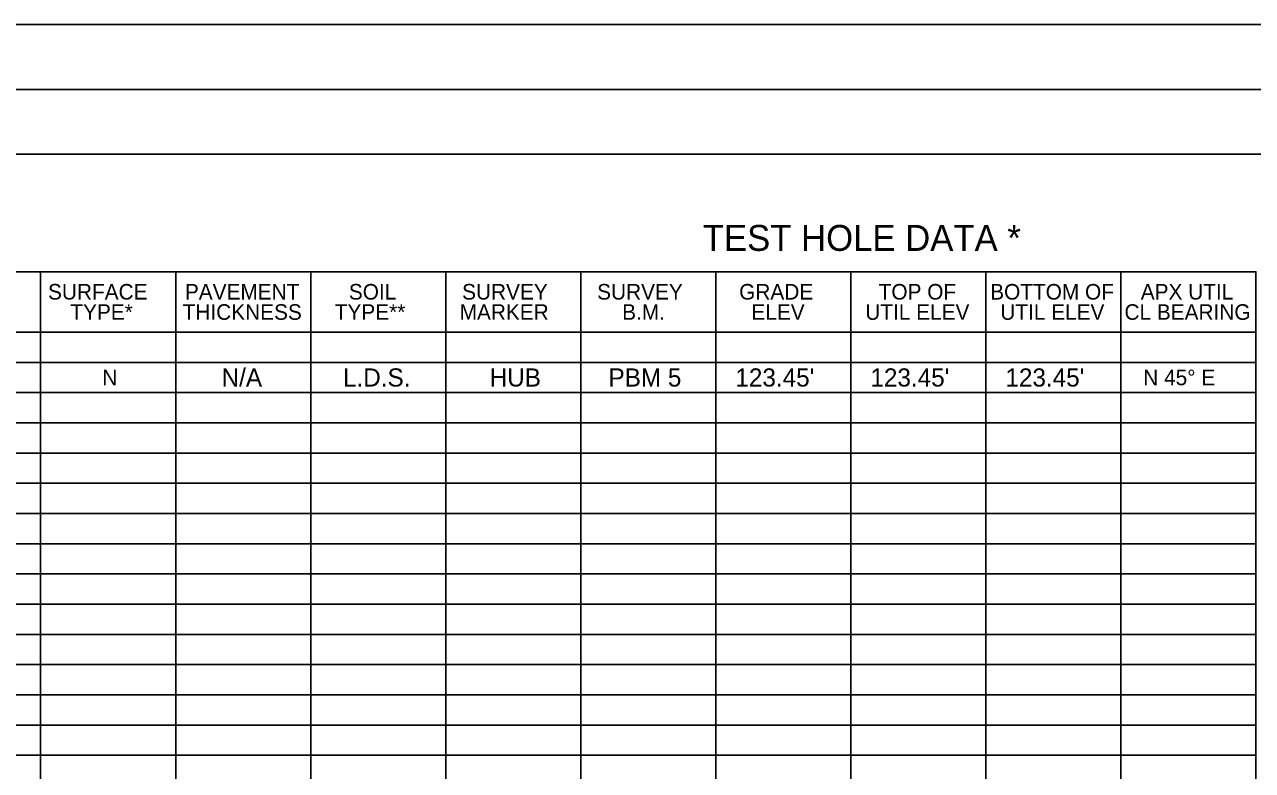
# Model space of a CAD drawing. Extents: x 14330 to 16126, y 15844 to 16994.
# Drawn here: x 14825 to 15298.3, y 16706 to 16993.6 of the extents above; entities that cross this region are included whole.
import ezdxf

# ---------------------------------------------------------------- set-up
doc = ezdxf.new("R2010")
doc.units = 0
for name, color, linetype in [('RD_SHT_Bndy', 7, 'Continuous'), ('RD_SHT_Iplotshp', 7, 'Continuous'), ('RD_SHT_TX', 7, 'Continuous')]:
    doc.layers.add(name, color=color, linetype=linetype)

msp = doc.modelspace()

# ---------------------------------------------------------------- linework, layer by layer
at = {"layer": 'RD_SHT_Bndy'}
for p, q in [((16108.25, 16993.63), (14348.25, 16993.63)), ((16108.25, 16968.63), (14348.25, 16968.63)), ((16105.85, 16943.63), (14430.85, 16943.63))]:
    msp.add_line(p, q, dxfattribs=at)
for points in [[(14779.19, 16875.02), (14831.23, 16875.02), (14831.23, 16898.33), (14779.19, 16898.33)], [(14831.23, 16875.02), (14883.27, 16875.02), (14883.27, 16898.33), (14831.23, 16898.33)], [(14883.27, 16875.02), (14935.31, 16875.02), (14935.31, 16898.33), (14883.27, 16898.33)], [(14935.31, 16875.02), (14987.35, 16875.02), (14987.35, 16898.33), (14935.31, 16898.33)], [(14987.35, 16875.02), (15039.39, 16875.02), (15039.39, 16898.33), (14987.35, 16898.33)], [(15039.39, 16875.02), (15091.44, 16875.02), (15091.44, 16898.33), (15039.39, 16898.33)], [(15091.44, 16875.02), (15143.48, 16875.02), (15143.48, 16898.33), (15091.44, 16898.33)], [(15143.48, 16875.02), (15195.52, 16875.02), (15195.52, 16898.33), (15143.48, 16898.33)], [(15195.52, 16875.02), (15247.56, 16875.02), (15247.56, 16898.33), (15195.52, 16898.33)], [(15247.56, 16875.02), (15299.6, 16875.02), (15299.6, 16898.33), (15247.56, 16898.33)], [(14831.23, 16863.36), (14779.19, 16863.36), (14779.19, 16875.02), (14831.23, 16875.02)], [(14883.27, 16863.36), (14831.23, 16863.36), (14831.23, 16875.02), (14883.27, 16875.02)], [(14935.31, 16863.36), (14883.27, 16863.36), (14883.27, 16875.02), (14935.31, 16875.02)], [(14987.35, 16863.36), (14935.31, 16863.36), (14935.31, 16875.02), (14987.35, 16875.02)], [(15039.39, 16863.36), (14987.35, 16863.36), (14987.35, 16875.02), (15039.39, 16875.02)], [(15091.44, 16863.36), (15039.39, 16863.36), (15039.39, 16875.02), (15091.44, 16875.02)], [(15143.48, 16863.36), (15091.44, 16863.36), (15091.44, 16875.02), (15143.48, 16875.02)], [(15195.52, 16863.36), (15143.48, 16863.36), (15143.48, 16875.02), (15195.52, 16875.02)], [(15247.56, 16863.36), (15195.52, 16863.36), (15195.52, 16875.02), (15247.56, 16875.02)], [(15299.6, 16863.36), (15247.56, 16863.36), (15247.56, 16875.02), (15299.6, 16875.02)], [(14831.23, 16851.71), (14779.19, 16851.71), (14779.19, 16863.36), (14831.23, 16863.36)], [(14883.27, 16851.71), (14831.23, 16851.71), (14831.23, 16863.36), (14883.27, 16863.36)], [(14935.31, 16851.71), (14883.27, 16851.71), (14883.27, 16863.36), (14935.31, 16863.36)], [(14987.35, 16851.71), (14935.31, 16851.71), (14935.31, 16863.36), (14987.35, 16863.36)], [(15039.39, 16851.71), (14987.35, 16851.71), (14987.35, 16863.36), (15039.39, 16863.36)], [(15091.44, 16851.71), (15039.39, 16851.71), (15039.39, 16863.36), (15091.44, 16863.36)], [(15143.48, 16851.71), (15091.44, 16851.71), (15091.44, 16863.36), (15143.48, 16863.36)], [(15195.52, 16851.71), (15143.48, 16851.71), (15143.48, 16863.36), (15195.52, 16863.36)], [(15247.56, 16851.71), (15195.52, 16851.71), (15195.52, 16863.36), (15247.56, 16863.36)], [(15299.6, 16851.71), (15247.56, 16851.71), (15247.56, 16863.36), (15299.6, 16863.36)], [(14831.23, 16840.05), (14779.19, 16840.05), (14779.19, 16851.71), (14831.23, 16851.71)], [(14883.27, 16840.05), (14831.23, 16840.05), (14831.23, 16851.71), (14883.27, 16851.71)], [(14935.31, 16840.05), (14883.27, 16840.05), (14883.27, 16851.71), (14935.31, 16851.71)], [(14987.35, 16840.05), (14935.31, 16840.05), (14935.31, 16851.71), (14987.35, 16851.71)], [(15039.39, 16840.05), (14987.35, 16840.05), (14987.35, 16851.71), (15039.39, 16851.71)], [(15091.44, 16840.05), (15039.39, 16840.05), (15039.39, 16851.71), (15091.44, 16851.71)], [(15143.48, 16840.05), (15091.44, 16840.05), (15091.44, 16851.71), (15143.48, 16851.71)], [(15195.52, 16840.05), (15143.48, 16840.05), (15143.48, 16851.71), (15195.52, 16851.71)], [(15247.56, 16840.05), (15195.52, 16840.05), (15195.52, 16851.71), (15247.56, 16851.71)], [(15299.6, 16840.05), (15247.56, 16840.05), (15247.56, 16851.71), (15299.6, 16851.71)], [(14831.23, 16828.4), (14779.19, 16828.4), (14779.19, 16840.05), (14831.23, 16840.05)], [(14883.27, 16828.4), (14831.23, 16828.4), (14831.23, 16840.05), (14883.27, 16840.05)], [(14935.31, 16828.4), (14883.27, 16828.4), (14883.27, 16840.05), (14935.31, 16840.05)], [(14987.35, 16828.4), (14935.31, 16828.4), (14935.31, 16840.05), (14987.35, 16840.05)], [(15039.39, 16828.4), (14987.35, 16828.4), (14987.35, 16840.05), (15039.39, 16840.05)], [(15091.44, 16828.4), (15039.39, 16828.4), (15039.39, 16840.05), (15091.44, 16840.05)], [(15143.48, 16828.4), (15091.44, 16828.4), (15091.44, 16840.05), (15143.48, 16840.05)], [(15195.52, 16828.4), (15143.48, 16828.4), (15143.48, 16840.05), (15195.52, 16840.05)], [(15247.56, 16828.4), (15195.52, 16828.4), (15195.52, 16840.05), (15247.56, 16840.05)], [(15299.6, 16828.4), (15247.56, 16828.4), (15247.56, 16840.05), (15299.6, 16840.05)], [(14831.23, 16816.74), (14779.19, 16816.74), (14779.19, 16828.4), (14831.23, 16828.4)], [(14883.27, 16816.74), (14831.23, 16816.74), (14831.23, 16828.4), (14883.27, 16828.4)], [(14935.31, 16816.74), (14883.27, 16816.74), (14883.27, 16828.4), (14935.31, 16828.4)], [(14987.35, 16816.74), (14935.31, 16816.74), (14935.31, 16828.4), (14987.35, 16828.4)], [(15039.39, 16816.74), (14987.35, 16816.74), (14987.35, 16828.4), (15039.39, 16828.4)], [(15091.44, 16816.74), (15039.39, 16816.74), (15039.39, 16828.4), (15091.44, 16828.4)], [(15143.48, 16816.74), (15091.44, 16816.74), (15091.44, 16828.4), (15143.48, 16828.4)], [(15195.52, 16816.74), (15143.48, 16816.74), (15143.48, 16828.4), (15195.52, 16828.4)], [(15247.56, 16816.74), (15195.52, 16816.74), (15195.52, 16828.4), (15247.56, 16828.4)], [(15299.6, 16816.74), (15247.56, 16816.74), (15247.56, 16828.4), (15299.6, 16828.4)], [(14831.23, 16805.09), (14779.19, 16805.09), (14779.19, 16816.74), (14831.23, 16816.74)], [(14883.27, 16805.09), (14831.23, 16805.09), (14831.23, 16816.74), (14883.27, 16816.74)], [(14935.31, 16805.09), (14883.27, 16805.09), (14883.27, 16816.74), (14935.31, 16816.74)], [(14987.35, 16805.09), (14935.31, 16805.09), (14935.31, 16816.74), (14987.35, 16816.74)], [(15039.39, 16805.09), (14987.35, 16805.09), (14987.35, 16816.74), (15039.39, 16816.74)], [(15091.44, 16805.09), (15039.39, 16805.09), (15039.39, 16816.74), (15091.44, 16816.74)], [(15143.48, 16805.09), (15091.44, 16805.09), (15091.44, 16816.74), (15143.48, 16816.74)], [(15195.52, 16805.09), (15143.48, 16805.09), (15143.48, 16816.74), (15195.52, 16816.74)], [(15247.56, 16805.09), (15195.52, 16805.09), (15195.52, 16816.74), (15247.56, 16816.74)], [(15299.6, 16805.09), (15247.56, 16805.09), (15247.56, 16816.74), (15299.6, 16816.74)], [(14831.23, 16793.43), (14779.19, 16793.43), (14779.19, 16805.09), (14831.23, 16805.09)], [(14883.27, 16793.43), (14831.23, 16793.43), (14831.23, 16805.09), (14883.27, 16805.09)], [(14935.31, 16793.43), (14883.27, 16793.43), (14883.27, 16805.09), (14935.31, 16805.09)], [(14987.35, 16793.43), (14935.31, 16793.43), (14935.31, 16805.09), (14987.35, 16805.09)], [(15039.39, 16793.43), (14987.35, 16793.43), (14987.35, 16805.09), (15039.39, 16805.09)], [(15091.44, 16793.43), (15039.39, 16793.43), (15039.39, 16805.09), (15091.44, 16805.09)], [(15143.48, 16793.43), (15091.44, 16793.43), (15091.44, 16805.09), (15143.48, 16805.09)], [(15195.52, 16793.43), (15143.48, 16793.43), (15143.48, 16805.09), (15195.52, 16805.09)], [(15247.56, 16793.43), (15195.52, 16793.43), (15195.52, 16805.09), (15247.56, 16805.09)], [(15299.6, 16793.43), (15247.56, 16793.43), (15247.56, 16805.09), (15299.6, 16805.09)], [(14831.23, 16781.78), (14779.19, 16781.78), (14779.19, 16793.43), (14831.23, 16793.43)], [(14883.27, 16781.78), (14831.23, 16781.78), (14831.23, 16793.43), (14883.27, 16793.43)], [(14935.31, 16781.78), (14883.27, 16781.78), (14883.27, 16793.43), (14935.31, 16793.43)], [(14987.35, 16781.78), (14935.31, 16781.78), (14935.31, 16793.43), (14987.35, 16793.43)], [(15039.39, 16781.78), (14987.35, 16781.78), (14987.35, 16793.43), (15039.39, 16793.43)], [(15091.44, 16781.78), (15039.39, 16781.78), (15039.39, 16793.43), (15091.44, 16793.43)], [(15143.48, 16781.78), (15091.44, 16781.78), (15091.44, 16793.43), (15143.48, 16793.43)], [(15195.52, 16781.78), (15143.48, 16781.78), (15143.48, 16793.43), (15195.52, 16793.43)], [(15247.56, 16781.78), (15195.52, 16781.78), (15195.52, 16793.43), (15247.56, 16793.43)], [(15299.6, 16781.78), (15247.56, 16781.78), (15247.56, 16793.43), (15299.6, 16793.43)], [(14831.23, 16770.12), (14779.19, 16770.12), (14779.19, 16781.78), (14831.23, 16781.78)], [(14883.27, 16770.12), (14831.23, 16770.12), (14831.23, 16781.78), (14883.27, 16781.78)], [(14935.31, 16770.12), (14883.27, 16770.12), (14883.27, 16781.78), (14935.31, 16781.78)], [(14987.35, 16770.12), (14935.31, 16770.12), (14935.31, 16781.78), (14987.35, 16781.78)], [(15039.39, 16770.12), (14987.35, 16770.12), (14987.35, 16781.78), (15039.39, 16781.78)], [(15091.44, 16770.12), (15039.39, 16770.12), (15039.39, 16781.78), (15091.44, 16781.78)], [(15143.48, 16770.12), (15091.44, 16770.12), (15091.44, 16781.78), (15143.48, 16781.78)], [(15195.52, 16770.12), (15143.48, 16770.12), (15143.48, 16781.78), (15195.52, 16781.78)], [(15247.56, 16770.12), (15195.52, 16770.12), (15195.52, 16781.78), (15247.56, 16781.78)], [(15299.6, 16770.12), (15247.56, 16770.12), (15247.56, 16781.78), (15299.6, 16781.78)], [(14831.23, 16758.47), (14779.19, 16758.47), (14779.19, 16770.12), (14831.23, 16770.12)], [(14883.27, 16758.47), (14831.23, 16758.47), (14831.23, 16770.12), (14883.27, 16770.12)], [(14935.31, 16758.47), (14883.27, 16758.47), (14883.27, 16770.12), (14935.31, 16770.12)], [(14987.35, 16758.47), (14935.31, 16758.47), (14935.31, 16770.12), (14987.35, 16770.12)], [(15039.39, 16758.47), (14987.35, 16758.47), (14987.35, 16770.12), (15039.39, 16770.12)], [(15091.44, 16758.47), (15039.39, 16758.47), (15039.39, 16770.12), (15091.44, 16770.12)], [(15143.48, 16758.47), (15091.44, 16758.47), (15091.44, 16770.12), (15143.48, 16770.12)], [(15195.52, 16758.47), (15143.48, 16758.47), (15143.48, 16770.12), (15195.52, 16770.12)], [(15247.56, 16758.47), (15195.52, 16758.47), (15195.52, 16770.12), (15247.56, 16770.12)], [(15299.6, 16758.47), (15247.56, 16758.47), (15247.56, 16770.12), (15299.6, 16770.12)], [(14831.23, 16746.81), (14779.19, 16746.81), (14779.19, 16758.47), (14831.23, 16758.47)], [(14883.27, 16746.81), (14831.23, 16746.81), (14831.23, 16758.47), (14883.27, 16758.47)], [(14935.31, 16746.81), (14883.27, 16746.81), (14883.27, 16758.47), (14935.31, 16758.47)], [(14987.35, 16746.81), (14935.31, 16746.81), (14935.31, 16758.47), (14987.35, 16758.47)], [(15039.39, 16746.81), (14987.35, 16746.81), (14987.35, 16758.47), (15039.39, 16758.47)], [(15091.44, 16746.81), (15039.39, 16746.81), (15039.39, 16758.47), (15091.44, 16758.47)], [(15143.48, 16746.81), (15091.44, 16746.81), (15091.44, 16758.47), (15143.48, 16758.47)], [(15195.52, 16746.81), (15143.48, 16746.81), (15143.48, 16758.47), (15195.52, 16758.47)], [(15247.56, 16746.81), (15195.52, 16746.81), (15195.52, 16758.47), (15247.56, 16758.47)], [(15299.6, 16746.81), (15247.56, 16746.81), (15247.56, 16758.47), (15299.6, 16758.47)], [(14831.23, 16735.16), (14779.19, 16735.16), (14779.19, 16746.81), (14831.23, 16746.81)], [(14883.27, 16735.16), (14831.23, 16735.16), (14831.23, 16746.81), (14883.27, 16746.81)], [(14935.31, 16735.16), (14883.27, 16735.16), (14883.27, 16746.81), (14935.31, 16746.81)], [(14987.35, 16735.16), (14935.31, 16735.16), (14935.31, 16746.81), (14987.35, 16746.81)], [(15039.39, 16735.16), (14987.35, 16735.16), (14987.35, 16746.81), (15039.39, 16746.81)], [(15091.44, 16735.16), (15039.39, 16735.16), (15039.39, 16746.81), (15091.44, 16746.81)], [(15143.48, 16735.16), (15091.44, 16735.16), (15091.44, 16746.81), (15143.48, 16746.81)], [(15195.52, 16735.16), (15143.48, 16735.16), (15143.48, 16746.81), (15195.52, 16746.81)], [(15247.56, 16735.16), (15195.52, 16735.16), (15195.52, 16746.81), (15247.56, 16746.81)], [(15299.6, 16735.16), (15247.56, 16735.16), (15247.56, 16746.81), (15299.6, 16746.81)], [(14831.23, 16723.5), (14779.19, 16723.5), (14779.19, 16735.16), (14831.23, 16735.16)], [(14883.27, 16723.5), (14831.23, 16723.5), (14831.23, 16735.16), (14883.27, 16735.16)], [(14935.31, 16723.5), (14883.27, 16723.5), (14883.27, 16735.16), (14935.31, 16735.16)], [(14987.35, 16723.5), (14935.31, 16723.5), (14935.31, 16735.16), (14987.35, 16735.16)], [(15039.39, 16723.5), (14987.35, 16723.5), (14987.35, 16735.16), (15039.39, 16735.16)], [(15091.44, 16723.5), (15039.39, 16723.5), (15039.39, 16735.16), (15091.44, 16735.16)], [(15143.48, 16723.5), (15091.44, 16723.5), (15091.44, 16735.16), (15143.48, 16735.16)], [(15195.52, 16723.5), (15143.48, 16723.5), (15143.48, 16735.16), (15195.52, 16735.16)], [(15247.56, 16723.5), (15195.52, 16723.5), (15195.52, 16735.16), (15247.56, 16735.16)], [(15299.6, 16723.5), (15247.56, 16723.5), (15247.56, 16735.16), (15299.6, 16735.16)], [(14831.23, 16711.84), (14779.19, 16711.84), (14779.19, 16723.5), (14831.23, 16723.5)], [(14883.27, 16711.84), (14831.23, 16711.84), (14831.23, 16723.5), (14883.27, 16723.5)], [(14935.31, 16711.84), (14883.27, 16711.84), (14883.27, 16723.5), (14935.31, 16723.5)], [(14987.35, 16711.84), (14935.31, 16711.84), (14935.31, 16723.5), (14987.35, 16723.5)], [(15039.39, 16711.84), (14987.35, 16711.84), (14987.35, 16723.5), (15039.39, 16723.5)], [(15091.44, 16711.84), (15039.39, 16711.84), (15039.39, 16723.5), (15091.44, 16723.5)], [(15143.48, 16711.84), (15091.44, 16711.84), (15091.44, 16723.5), (15143.48, 16723.5)], [(15195.52, 16711.84), (15143.48, 16711.84), (15143.48, 16723.5), (15195.52, 16723.5)], [(15247.56, 16711.84), (15195.52, 16711.84), (15195.52, 16723.5), (15247.56, 16723.5)], [(15299.6, 16711.84), (15247.56, 16711.84), (15247.56, 16723.5), (15299.6, 16723.5)], [(14831.23, 16700.19), (14779.19, 16700.19), (14779.19, 16711.84), (14831.23, 16711.84)], [(14883.27, 16700.19), (14831.23, 16700.19), (14831.23, 16711.84), (14883.27, 16711.84)], [(14935.31, 16700.19), (14883.27, 16700.19), (14883.27, 16711.84), (14935.31, 16711.84)], [(14987.35, 16700.19), (14935.31, 16700.19), (14935.31, 16711.84), (14987.35, 16711.84)], [(15039.39, 16700.19), (14987.35, 16700.19), (14987.35, 16711.84), (15039.39, 16711.84)], [(15091.44, 16700.19), (15039.39, 16700.19), (15039.39, 16711.84), (15091.44, 16711.84)], [(15143.48, 16700.19), (15091.44, 16700.19), (15091.44, 16711.84), (15143.48, 16711.84)], [(15195.52, 16700.19), (15143.48, 16700.19), (15143.48, 16711.84), (15195.52, 16711.84)], [(15247.56, 16700.19), (15195.52, 16700.19), (15195.52, 16711.84), (15247.56, 16711.84)], [(15299.6, 16700.19), (15247.56, 16700.19), (15247.56, 16711.84), (15299.6, 16711.84)]]:
    msp.add_lwpolyline(points, close=True, dxfattribs=at)
at = {"layer": 'RD_SHT_Iplotshp'}
msp.add_lwpolyline([(14329.65, 16968.63), (16125.65, 16968.63), (16125.65, 15868.63), (14329.65, 15868.63)], close=True, dxfattribs=at)

# ---------------------------------------------------------------- texts
at = {"layer": 'RD_SHT_TX'}
for s, height, p in [('TEST HOLE DATA *', 10, (15086.42, 16906.35)), ('SURFACE', 6, (14834.07, 16887.58)), ('PAVEMENT', 6, (14886.82, 16887.58)), ('SOIL', 6, (14950.02, 16887.58)), ('SURVEY', 6, (14993.67, 16887.58)), ('SURVEY', 6, (15045.72, 16887.58)), ('GRADE', 6, (15100.45, 16887.58)), ('TOP OF', 6, (15154.22, 16887.58)), ('BOTTOM OF', 6, (15197.2, 16887.58)), ('APX UTIL', 6, (15255.24, 16887.58)), ('TYPE*', 6, (14842.68, 16879.77)), ('THICKNESS', 6, (14885.97, 16879.77)), ('TYPE**', 6, (14944.58, 16879.77)), ('MARKER', 6, (14992.72, 16879.77)), ('B.M.', 6, (15055.35, 16879.77)), ('ELEV', 6, (15105.18, 16879.77)), ('UTIL ELEV', 6, (15149.06, 16879.77)), ('UTIL ELEV', 6, (15201.1, 16879.77)), ('CL BEARING', 6, (15248.95, 16879.77)), ('N', 6, (14854.98, 16854.53)), ('N/A', 7, (14900.97, 16854.03)), ('L.D.S.', 7, (14947.75, 16854.03)), ('HUB', 7, (15004.28, 16854.03)), ('PBM 5', 7, (15050.09, 16854.03)), ("123.45'", 7, (15098.99, 16854.03)), ("123.45'", 7, (15151.03, 16854.03)), ("123.45'", 7, (15203.07, 16854.03)), ('N 45%%d E', 6, (15256.19, 16854.53))]:
    msp.add_text(s, height=height, dxfattribs=at).set_placement(p)

doc.saveas('drawing.dxf')
